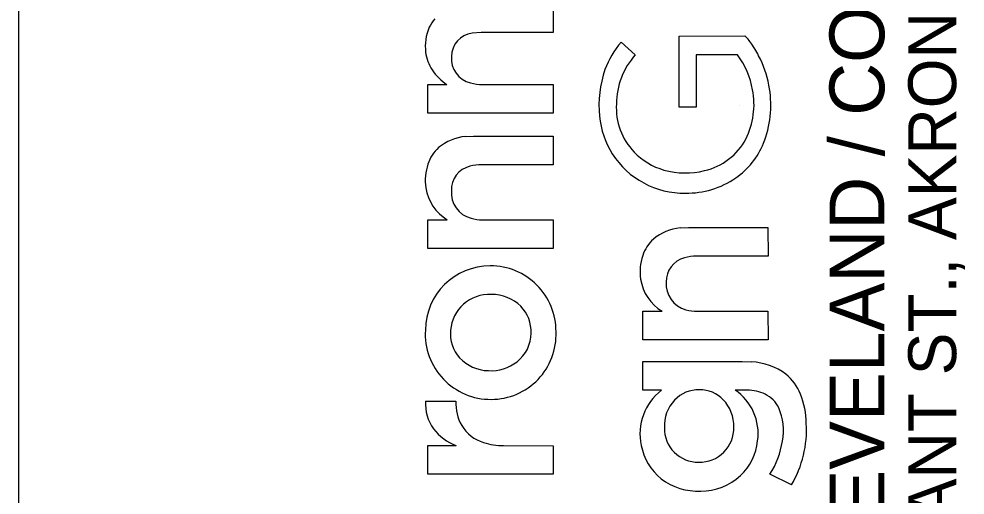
# Model space of a CAD drawing. Extents: x -0.3 to 34, y 0 to 22.
# Drawn here: x 32 to 32.984, y 3.094 to 3.59 of the extents above; entities that cross this region are included whole.
import ezdxf

# ---------------------------------------------------------------- set-up
doc = ezdxf.new("R2010")
doc.units = 0
doc.layers.add('SH_Border', color=7, linetype='Continuous')
doc.layers.add('SH_Data', color=7, linetype='Continuous')

msp = doc.modelspace()

# ---------------------------------------------------------------- linework, layer by layer
at = {"layer": 'SH_Border'}
msp.add_line((32, 0.5), (32, 21.5), dxfattribs=at)
at = {"layer": 'SH_Data'}
for p, q in [((32.55571, 3.60548), (32.55571, 3.57568)), ((32.4809, 3.57567), (32.47143, 3.57474)), ((32.55571, 3.57568), (32.4809, 3.57567)), ((32.62636, 3.56548), (32.64114, 3.55241)), ((32.6868, 3.57185), (32.75516, 3.57192)), ((32.6868, 3.49778), (32.6868, 3.57185)), ((32.70448, 3.55241), (32.70432, 3.49775)), ((32.74737, 3.55227), (32.70448, 3.55241)), ((32.42542, 3.49152), (32.42545, 3.52138)), ((32.42545, 3.52138), (32.44515, 3.52138)), ((32.48206, 3.52138), (32.55571, 3.52136)), ((32.55571, 3.52136), (32.55571, 3.49156)), ((32.70432, 3.49775), (32.6868, 3.49778)), ((32.75, 3.5), (32.75, 3.5)), ((32.55571, 3.49156), (32.42542, 3.49152)), ((32.46439, 3.46736), (32.47289, 3.46783)), ((32.47289, 3.46783), (32.55571, 3.46783)), ((32.55571, 3.46783), (32.55571, 3.43804)), ((32.55571, 3.43804), (32.4814, 3.43796)), ((32.42542, 3.38066), (32.44552, 3.38071)), ((32.42542, 3.35086), (32.42542, 3.38066)), ((32.48222, 3.38071), (32.55569, 3.38071)), ((32.55569, 3.38071), (32.55571, 3.35096)), ((32.68784, 3.3722), (32.69634, 3.37266)), ((32.69634, 3.37266), (32.77916, 3.37266)), ((32.77916, 3.37266), (32.77917, 3.34287)), ((32.55571, 3.35096), (32.42542, 3.35086)), ((32.77917, 3.34287), (32.70485, 3.3428)), ((32.64888, 3.2855), (32.66897, 3.28555)), ((32.64888, 3.25569), (32.64888, 3.2855)), ((32.70568, 3.28555), (32.77915, 3.28555)), ((32.77915, 3.28555), (32.77917, 3.25579)), ((32.77917, 3.25579), (32.64888, 3.25569)), ((32.6489, 3.20336), (32.64889, 3.23322)), ((32.64889, 3.23322), (32.75236, 3.23322)), ((32.75236, 3.23322), (32.76191, 3.23285)), ((32.66836, 3.20336), (32.6489, 3.20336)), ((32.75763, 3.20356), (32.74487, 3.20361)), ((32.42299, 3.19193), (32.45454, 3.19193)), ((32.42542, 3.14577), (32.45473, 3.14579)), ((32.42542, 3.11593), (32.42542, 3.14577)), ((32.50413, 3.14581), (32.55571, 3.14573)), ((32.55571, 3.14573), (32.55565, 3.11593)), ((32.55565, 3.11593), (32.42542, 3.11593)), ((32.8036, 3.10491), (32.7812, 3.11598))]:
    msp.add_line(p, q, dxfattribs=at)
for points in [[(32.48218, 3.60553), (32.55571, 3.60548), (32.55571, 3.57568), (32.4809, 3.57567), (32.47143, 3.57474)], [(32.62636, 3.56548), (32.64114, 3.55241)], [(32.74737, 3.55227), (32.70448, 3.55241), (32.70432, 3.49775), (32.6868, 3.49778), (32.6868, 3.57185), (32.75516, 3.57192)], [(32.42542, 3.49152), (32.42545, 3.52138), (32.44515, 3.52138)], [(32.48206, 3.52138), (32.55571, 3.52136), (32.55571, 3.49156), (32.42542, 3.49152)], [(32.46439, 3.46736), (32.47289, 3.46783), (32.55571, 3.46783), (32.55571, 3.43804), (32.4814, 3.43796)], [(32.42542, 3.35086), (32.42542, 3.38066), (32.44552, 3.38071)], [(32.48222, 3.38071), (32.55569, 3.38071), (32.55571, 3.35096), (32.42542, 3.35086)], [(32.68784, 3.3722), (32.69634, 3.37266), (32.77916, 3.37266), (32.77917, 3.34287), (32.70485, 3.3428)], [(32.64888, 3.25569), (32.64888, 3.2855), (32.66897, 3.28555)], [(32.70568, 3.28555), (32.77915, 3.28555), (32.77917, 3.25579), (32.64888, 3.25569)], [(32.66836, 3.20336), (32.6489, 3.20336), (32.64889, 3.23322), (32.75236, 3.23322), (32.76191, 3.23285)], [(32.75763, 3.20356), (32.74487, 3.20361)], [(32.42299, 3.19193), (32.45454, 3.19193)], [(32.50413, 3.14581), (32.55571, 3.14573), (32.55565, 3.11593), (32.42542, 3.11593)], [(32.42542, 3.11593), (32.42542, 3.14577), (32.45473, 3.14579)], [(32.8036, 3.10491), (32.7812, 3.11598)]]:
    msp.add_lwpolyline(points, dxfattribs=at)
for centre, radius, start, end in [((32.46194, 3.56452), 0.03875, 139.52447, 154.84698), ((32.46194, 3.56452), 0.03875, 139.52447, 154.84698), ((32.47144, 3.5612), 0.04877, 156.06382, 187.3493), ((32.47144, 3.5612), 0.04877, 156.06382, 187.3493), ((32.47421, 3.55056), 0.02434, 96.5532, 179.94902), ((32.47421, 3.55056), 0.02434, 96.5532, 179.94902), ((32.70163, 3.50187), 0.09855, 139.79476, 159.13696), ((32.70163, 3.50187), 0.09855, 139.79476, 159.13696), ((32.72498, 3.53937), 0.04438, 30.98913, 47.16099), ((32.72498, 3.53937), 0.04438, 30.98913, 47.16099), ((32.46461, 3.55974), 0.04181, 186.5579, 213.38846), ((32.46461, 3.55974), 0.04181, 186.5579, 213.38846), ((32.67091, 3.50018), 0.11106, 25.30315, 33.96179), ((32.67091, 3.50018), 0.11106, 25.30315, 33.96179), ((32.47608, 3.54863), 0.02628, 175.722, 255.78627), ((32.47608, 3.54863), 0.02628, 175.722, 255.78627), ((32.69899, 3.50079), 0.07753, 138.25804, 179.70064), ((32.69899, 3.50079), 0.07753, 138.25804, 179.70064), ((32.67889, 3.50099), 0.08556, 10.07509, 36.83189), ((32.67889, 3.50099), 0.08556, 10.07509, 36.83189), ((32.6704, 3.49987), 0.11166, 8.80339, 25.33484), ((32.6704, 3.49987), 0.11166, 8.80339, 25.33484), ((32.47886, 3.57078), 0.0598, 214.70433, 235.68724), ((32.47886, 3.57078), 0.0598, 214.70433, 235.68724), ((32.7187, 3.49968), 0.11536, 161.14379, 185.62812), ((32.7187, 3.49968), 0.11536, 161.14379, 185.62812), ((32.48195, 3.56518), 0.0438, 253.66719, 270.14979), ((32.48195, 3.56518), 0.0438, 253.66719, 270.14979), ((32.68425, 3.50057), 0.08036, 333.46689, 11.03668), ((32.68425, 3.50057), 0.08036, 333.46689, 11.03668), ((32.67564, 3.49977), 0.10649, 338.28866, 9.28548), ((32.67564, 3.49977), 0.10649, 338.28866, 9.28548), ((32.68811, 3.49732), 0.06676, 176.66577, 223.6912), ((32.68811, 3.49732), 0.06676, 176.66577, 223.6912), ((32.69336, 3.49699), 0.08987, 185.50773, 212.01294), ((32.69336, 3.49699), 0.08987, 185.50773, 212.01294), ((32.46871, 3.41767), 0.04988, 94.97056, 130.22484), ((32.46871, 3.41767), 0.04988, 94.97056, 130.22484), ((32.69868, 3.49547), 0.0652, 282.88151, 331.81475), ((32.69868, 3.49547), 0.0652, 282.88151, 331.81475), ((32.46348, 3.42602), 0.04016, 132.22383, 161.68229), ((32.46348, 3.42602), 0.04016, 132.22383, 161.68229), ((32.69835, 3.49168), 0.08241, 305.03061, 337.67573), ((32.69835, 3.49168), 0.08241, 305.03061, 337.67573), ((32.69211, 3.49748), 0.08908, 212.70222, 270.71399), ((32.69211, 3.49748), 0.08908, 212.70222, 270.71399), ((32.69045, 3.50011), 0.07039, 224.02147, 253.88), ((32.69045, 3.50011), 0.07039, 224.02147, 253.88), ((32.47872, 3.42158), 0.05602, 162.27398, 187.79173), ((32.47872, 3.42158), 0.05602, 162.27398, 187.79173), ((32.47482, 3.41206), 0.02498, 103.68683, 182.21395), ((32.47482, 3.41206), 0.02498, 103.68683, 182.21395), ((32.48108, 3.39196), 0.04601, 89.60515, 105.33026), ((32.48108, 3.39196), 0.04601, 89.60515, 105.33026), ((32.69318, 3.51254), 0.08309, 254.45353, 283.9512), ((32.69318, 3.51254), 0.08309, 254.45353, 283.9512), ((32.69429, 3.49979), 0.09138, 269.3273, 304.19632), ((32.69429, 3.49979), 0.09138, 269.3273, 304.19632), ((32.47027, 3.42141), 0.04763, 188.96462, 238.69865), ((32.47027, 3.42141), 0.04763, 188.96462, 238.69865), ((32.47735, 3.40897), 0.02757, 175.58441, 255.13816), ((32.47735, 3.40897), 0.02757, 175.58441, 255.13816), ((32.48183, 3.42286), 0.04215, 254.08913, 270.52838), ((32.48183, 3.42286), 0.04215, 254.08913, 270.52838), ((32.69216, 3.32251), 0.04988, 94.97056, 130.22484), ((32.69216, 3.32251), 0.04988, 94.97056, 130.22484), ((32.68694, 3.33085), 0.04016, 132.22383, 161.68229), ((32.68694, 3.33085), 0.04016, 132.22383, 161.68229), ((32.70217, 3.32642), 0.05602, 162.27398, 187.79173), ((32.70217, 3.32642), 0.05602, 162.27398, 187.79173), ((32.69828, 3.31689), 0.02498, 103.68683, 182.21395), ((32.69828, 3.31689), 0.02498, 103.68683, 182.21395), ((32.70453, 3.29679), 0.04601, 89.60515, 105.33026), ((32.70453, 3.29679), 0.04601, 89.60515, 105.33026), ((32.49014, 3.26543), 0.0674, 89.84756, 179.64047), ((32.49014, 3.26543), 0.0674, 89.84756, 179.64047), ((32.49057, 3.26474), 0.0681, 359.54009, 90.21138), ((32.49057, 3.26474), 0.0681, 359.54009, 90.21138), ((32.69372, 3.32624), 0.04763, 188.96462, 238.69865), ((32.69372, 3.32624), 0.04763, 188.96462, 238.69865), ((32.7008, 3.31381), 0.02757, 175.58441, 255.13816), ((32.7008, 3.31381), 0.02757, 175.58441, 255.13816), ((32.48923, 3.26263), 0.0404, 87.04809, 175.57259), ((32.48923, 3.26263), 0.0404, 87.04809, 175.57259), ((32.49204, 3.25999), 0.04299, 45.84264, 90.98008), ((32.49204, 3.25999), 0.04299, 45.84264, 90.98008), ((32.49458, 3.26421), 0.03821, 357.88569, 44.15902), ((32.49458, 3.26421), 0.03821, 357.88569, 44.15902), ((32.70529, 3.32769), 0.04215, 254.08913, 270.52838), ((32.70529, 3.32769), 0.04215, 254.08913, 270.52838), ((32.49083, 3.26209), 0.06819, 176.8344, 270.40384), ((32.49083, 3.26209), 0.06819, 176.8344, 270.40384), ((32.48729, 3.2625), 0.03848, 175.15378, 221.14706), ((32.48729, 3.2625), 0.03848, 175.15378, 221.14706), ((32.49123, 3.26139), 0.06749, 270.06243, 2.37759), ((32.49123, 3.26139), 0.06749, 270.06243, 2.37759), ((32.49446, 3.26318), 0.0383, 308.28936, 359.43468), ((32.49446, 3.26318), 0.0383, 308.28936, 359.43468), ((32.48919, 3.26607), 0.04228, 223.09994, 268.80895), ((32.48919, 3.26607), 0.04228, 223.09994, 268.80895), ((32.49096, 3.2679), 0.04418, 266.56515, 308.06078), ((32.49096, 3.2679), 0.04418, 266.56515, 308.06078), ((32.75907, 3.16789), 0.06503, 53.40344, 87.49062), ((32.75907, 3.16789), 0.06503, 53.40344, 87.49062), ((32.76517, 3.18039), 0.05141, 21.60748, 50.5577), ((32.76517, 3.18039), 0.05141, 21.60748, 50.5577), ((32.70292, 3.15813), 0.05692, 127.37482, 192.22468), ((32.70292, 3.15813), 0.05692, 127.37482, 192.22468), ((32.70693, 3.16927), 0.0346, 88.47302, 136.42562), ((32.70693, 3.16927), 0.0346, 88.47302, 136.42562), ((32.70814, 3.16963), 0.03424, 44.27195, 90.47623), ((32.70814, 3.16963), 0.03424, 44.27195, 90.47623), ((32.71421, 3.15829), 0.05472, 352.1125, 55.92295), ((32.71421, 3.15829), 0.05472, 352.1125, 55.92295), ((32.75666, 3.15725), 0.04633, 65.01687, 88.8011), ((32.75666, 3.15725), 0.04633, 65.01687, 88.8011), ((32.7626, 3.17155), 0.03085, 26.26808, 63.80301), ((32.7626, 3.17155), 0.03085, 26.26808, 63.80301), ((32.73069, 3.16714), 0.08835, 1.15143, 21.3627), ((32.73069, 3.16714), 0.08835, 1.15143, 21.3627), ((32.46616, 3.18882), 0.04329, 175.87313, 216.34747), ((32.46616, 3.18882), 0.04329, 175.87313, 216.34747), ((32.50087, 3.18948), 0.04639, 176.9688, 209.60636), ((32.50087, 3.18948), 0.04639, 176.9688, 209.60636), ((32.71141, 3.16602), 0.0401, 137.46739, 182.33237), ((32.71141, 3.16602), 0.0401, 137.46739, 182.33237), ((32.70368, 3.166), 0.03996, 358.57141, 43.53765), ((32.70368, 3.166), 0.03996, 358.57141, 43.53765), ((32.73565, 3.16154), 0.05953, 349.30734, 23.43071), ((32.73565, 3.16154), 0.05953, 349.30734, 23.43071), ((32.47466, 3.19716), 0.05511, 218.09809, 248.7907), ((32.47466, 3.19716), 0.05511, 218.09809, 248.7907), ((32.49514, 3.18814), 0.04079, 211.94466, 253.2028), ((32.49514, 3.18814), 0.04079, 211.94466, 253.2028), ((32.70645, 3.1637), 0.03511, 178.88208, 271.08374), ((32.70645, 3.1637), 0.03511, 178.88208, 271.08374), ((32.70818, 3.16404), 0.03546, 268.27882, 1.55016), ((32.70818, 3.16404), 0.03546, 268.27882, 1.55016), ((32.70538, 3.16244), 0.11383, 329.6388, 3.25998), ((32.70538, 3.16244), 0.11383, 329.6388, 3.25998), ((32.70988, 3.15708), 0.05887, 313.74196, 353.8554), ((32.70988, 3.15708), 0.05887, 313.74196, 353.8554), ((32.70738, 3.16334), 0.08771, 327.31495, 351.57478), ((32.70738, 3.16334), 0.08771, 327.31495, 351.57478), ((32.50465, 3.2165), 0.07069, 252.46555, 269.57296), ((32.50465, 3.2165), 0.07069, 252.46555, 269.57296), ((32.70463, 3.15696), 0.05837, 190.75182, 231.28919), ((32.70463, 3.15696), 0.05837, 190.75182, 231.28919), ((32.70632, 3.16112), 0.06269, 232.46061, 272.59022), ((32.70632, 3.16112), 0.06269, 232.46061, 272.59022), ((32.70954, 3.15901), 0.06051, 269.6361, 312.70877), ((32.70954, 3.15901), 0.06051, 269.6361, 312.70877)]:
    msp.add_arc(centre, radius, start, end, dxfattribs=at)

# ---------------------------------------------------------------- texts
for s, height, p in [('450 GRANT ST., AKRON, OH  44311', 0.0498462, (32.97489, 2.83738)), ('AKRON / CLEVELAND / COLUMBUS', 0.056969, (32.90012, 2.638))]:
    msp.add_text(s, height=height, rotation=90, dxfattribs=at).set_placement(p)

doc.saveas('drawing.dxf')
